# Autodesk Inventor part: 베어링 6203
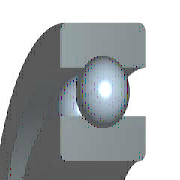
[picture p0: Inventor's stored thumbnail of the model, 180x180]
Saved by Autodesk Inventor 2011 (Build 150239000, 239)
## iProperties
IsCustomPart: 0
Created: 2009-02
Part Number: 베어링 6203
Material: 강, 연강
Description: 깊은 그루브 볼 베어링
Document SubType Name: Modeling
Standard: KS B 2023
Designer: 한국산업디자인학원 [http://gmhk.co.kr]
Standards Organization: KS
Language: ko-KR
Size Designation: 6203 - 17 x 40 x 12
Categories: <MemberInstance><Categories><Category DisplayName="샤프트 부품" InternalName="7f7aeb1f-a693-4053-b835-cee3144e0d98" Mnemonic="SHFT"><Category DisplayName="베어링" Inter
Density: 1 g/cm^3
Author: pww
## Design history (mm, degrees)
revolve "본체" stored, may be unused: angle "d6" = 90 deg
revolve "볼" stored, may be unused: angle "d7" = 90 deg
pattern_circular "IDS_ARRAYBALL[SIMPL:T]" dims angle "d3" = 360 deg
body "Solid1"
sketch "스케치" dims "d0" = 5.98 (= -0.26 x WD + 0.26 x BD)
  geometry: L1 (3.01, 14.25)-(8.99, 14.25); L2 (6, 14.25)-(6, 11.26); L3 (6, 14.25)-(6, 17.24); L4 (3.778, 12.249)-(0, 12.249); L5 (0, 8.5)-(12, 8.5); L6 (3.778, 16.251)-(0, 16.251); L7 (0, 20)-(12, 20); L8 (12, 8.5)-(12, 12.249); L9 (8.222, 12.249)-(12, 12.249); L10 (8.222, 16.251)-(12, 16.251); L11 (12, 20)-(12, 16.251); L12 (-1.4, 0)-(8.4, 0) reference; L13 (0, -0.3)-(0, 5.3) reference
  constraints: 22 end point, 4 point on line, 2 collinear, 2 perpendicular, 2 symmetric about line, 1 midpoint, 1 parallel, 14 other
  dimensions: "d9" = 17 diameter of L5 L12 (= WD); "d11" = 40 diameter of L7 L12 (= BD); "d12" = 12 distance between parallel lines of L8 L13 (= KB); "d13" = 24.498 diameter of L9 L12 (= 0.326 x BD + 0.674 x WD)
fillet "모깎기1" dims "d1" = 0.6 (= KRS)
other parameters: "WD" = 17 [user parameter; used in 5 equation terms], "BD" = 40 [user parameter; used in 5 equation terms], "KB" = 12 [user parameter; used in 1 equation term], "KRS" = 0.6 [user parameter; used in 1 equation term], "d4" = 0, "d5" = 0, "d8" = 0, "d14" = 0, "d15" = 0, "BBA" = 0 [user parameter], "BC0" = 4750000 [user parameter], "BC" = 9560000 [user parameter], "WR" = 8.5 (= 0.5 x WD) [user parameter]
